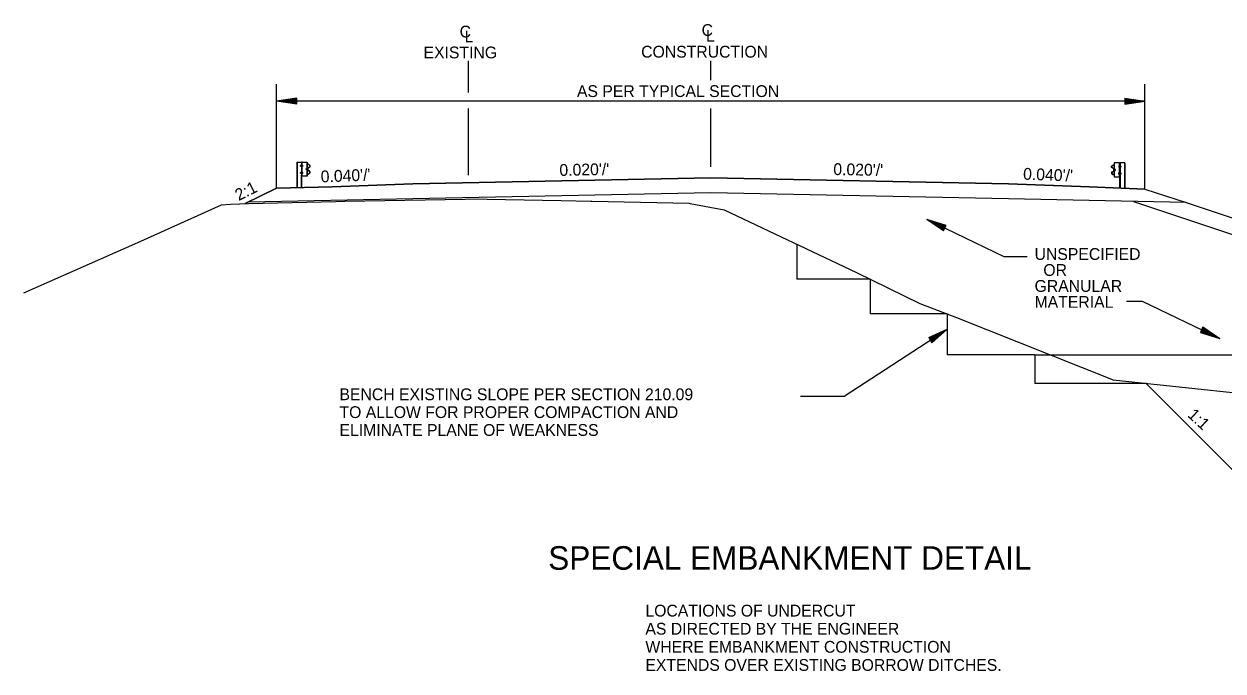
# Model space of a CAD drawing. Extents: x 1035 to 3550, y 35 to 1510.
# Drawn here: x 2159 to 2769, y 1181 to 1510 of the extents above; entities that cross this region are included whole.
import ezdxf

# ---------------------------------------------------------------- set-up
doc = ezdxf.new("R2010")
doc.units = 0
for name, color, linetype in [('G-ANNO-NPLT', 7, 'Continuous'), ('R_Alt Surface', 7, 'Continuous'), ('R_Border Notes', 7, 'Continuous'), ('R_Border Prem', 7, 'Continuous'), ('R_Exist Surface', 7, 'Continuous'), ('R_Fin Surface', 7, 'Continuous'), ('R_Grid', 7, 'Continuous')]:
    doc.layers.add(name, color=color, linetype=linetype)

msp = doc.modelspace()

# ---------------------------------------------------------------- linework, layer by layer
at = {"layer": 'G-ANNO-NPLT'}
for p, q in [((2385.15, 1474.91), (2385.15, 1491.12)), ((2508.51, 1481.13), (2508.51, 1491.12)), ((2385.15, 1432.87), (2385.15, 1466.73)), ((2508.51, 1437.15), (2508.51, 1466.73)), ((2297.65, 1439.46), (2297.65, 1426.52)), ((2297.81, 1439.46), (2297.81, 1426.52)), ((2299.71, 1437.35), (2299.71, 1437.83)), ((2299.99, 1437.76), (2299.74, 1437.76)), ((2299.99, 1437.43), (2299.74, 1437.43)), ((2299.99, 1437.27), (2299.74, 1437.27)), ((2299.99, 1437.91), (2299.75, 1437.91)), ((2299.99, 1437.43), (2299.77, 1437.43)), ((2299.99, 1437.27), (2299.99, 1437.91)), ((2300.35, 1439.47), (2300, 1439.45)), ((2300.18, 1426.52), (2300.18, 1439.47)), ((2300.35, 1439.47), (2300.32, 1439.47)), ((2300.64, 1437.56), (2300.35, 1437.56)), ((2300.38, 1437.24), (2300.64, 1437.24)), ((2300.39, 1437.89), (2300.64, 1437.89)), ((2300.64, 1437.89), (2300.64, 1437.24)), ((2302.57, 1435.69), (2302.57, 1436.18)), ((2302.85, 1436.1), (2302.6, 1436.1)), ((2302.85, 1435.77), (2302.6, 1435.77)), ((2302.85, 1435.62), (2302.6, 1435.62)), ((2302.85, 1436.26), (2302.61, 1436.26)), ((2302.85, 1435.77), (2302.63, 1435.77)), ((2302.85, 1435.62), (2302.85, 1436.26)), ((2302.92, 1432.43), (2302.92, 1439.43)), ((2303.66, 1438.36), (2303.08, 1438.67)), ((2303.59, 1438.28), (2303.12, 1438.53)), ((2303.12, 1435.62), (2303.13, 1436.3)), ((2303.24, 1435.62), (2303.25, 1436.3)), ((2304.13, 1434.74), (2303.34, 1435.24)), ((2303.36, 1436.65), (2304.25, 1437.19)), ((2304.2, 1434.84), (2303.4, 1435.34)), ((2303.43, 1436.54), (2304.31, 1437.08)), ((2304.26, 1437.74), (2303.59, 1438.28)), ((2304.33, 1437.82), (2303.66, 1438.36)), ((2712.67, 1437.46), (2713.34, 1438)), ((2713.57, 1436.18), (2712.69, 1436.72)), ((2712.74, 1437.38), (2713.41, 1437.92)), ((2713.64, 1436.29), (2712.76, 1436.83)), ((2713.34, 1438), (2713.92, 1438.31)), ((2713.41, 1437.92), (2713.89, 1438.17)), ((2713.76, 1435.26), (2713.75, 1435.94)), ((2713.88, 1435.26), (2713.87, 1435.94)), ((2714.08, 1432.07), (2714.08, 1439.07)), ((2714.15, 1435.26), (2714.15, 1435.9)), ((2714.15, 1435.9), (2714.4, 1435.9)), ((2714.15, 1435.74), (2714.4, 1435.74)), ((2714.15, 1435.41), (2714.37, 1435.41)), ((2714.15, 1435.41), (2714.4, 1435.41)), ((2714.15, 1435.26), (2714.41, 1435.26)), ((2714.43, 1435.34), (2714.43, 1435.82)), ((2716.61, 1437.53), (2716.36, 1437.53)), ((2716.36, 1437.53), (2716.36, 1436.88)), ((2716.62, 1436.88), (2716.36, 1436.88)), ((2716.37, 1437.2), (2716.66, 1437.2)), ((2716.65, 1439.11), (2716.68, 1439.11)), ((2716.65, 1439.11), (2717.01, 1439.09)), ((2716.83, 1426.16), (2716.83, 1439.11)), ((2717.01, 1436.91), (2717.01, 1437.55)), ((2717.01, 1437.55), (2717.26, 1437.55)), ((2717.01, 1437.4), (2717.26, 1437.4)), ((2717.01, 1437.07), (2717.23, 1437.07)), ((2717.01, 1437.07), (2717.26, 1437.07)), ((2717.01, 1436.91), (2717.27, 1436.91)), ((2717.29, 1436.99), (2717.29, 1437.47)), ((2719.2, 1439.1), (2719.2, 1426.16)), ((2719.35, 1439.1), (2719.35, 1426.16)), ((2299.66, 1433.8), (2299.66, 1434.29)), ((2299.94, 1434.37), (2299.69, 1434.37)), ((2299.94, 1434.21), (2299.69, 1434.21)), ((2299.94, 1433.88), (2299.69, 1433.88)), ((2299.94, 1433.72), (2299.69, 1433.72)), ((2299.94, 1433.88), (2299.72, 1433.88)), ((2299.94, 1433.72), (2299.94, 1434.37)), ((2300.35, 1432.43), (2300.17, 1432.43)), ((2300.64, 1434.04), (2300.35, 1434.04)), ((2300.64, 1433.72), (2300.38, 1433.72)), ((2300.64, 1434.37), (2300.39, 1434.37)), ((2300.64, 1433.72), (2300.64, 1434.37)), ((2303.06, 1433.27), (2303.62, 1433.55)), ((2303.11, 1433.17), (2303.69, 1433.47)), ((2303.62, 1433.55), (2304.27, 1434.11)), ((2303.69, 1433.47), (2304.34, 1434.03)), ((2713.31, 1433.11), (2712.66, 1433.67)), ((2713.38, 1433.19), (2712.74, 1433.75)), ((2712.81, 1434.48), (2713.6, 1434.98)), ((2712.87, 1434.38), (2713.67, 1434.88)), ((2713.9, 1432.81), (2713.31, 1433.11)), ((2713.94, 1432.91), (2713.38, 1433.19)), ((2716.36, 1433.37), (2716.36, 1434.01)), ((2716.36, 1434.01), (2716.61, 1434.01)), ((2716.36, 1433.37), (2716.62, 1433.37)), ((2716.37, 1433.68), (2716.66, 1433.68)), ((2716.66, 1432.07), (2716.83, 1432.07)), ((2717.06, 1433.37), (2717.06, 1434.01)), ((2717.06, 1434.01), (2717.31, 1434.01)), ((2717.06, 1433.85), (2717.32, 1433.85)), ((2717.06, 1433.52), (2717.28, 1433.52)), ((2717.06, 1433.52), (2717.32, 1433.52)), ((2717.06, 1433.37), (2717.32, 1433.37)), ((2717.34, 1433.44), (2717.34, 1433.93)), ((2287.37, 1426.32), (2271.45, 1418.36)), ((2315.65, 1426.88), (2287.37, 1426.32)), ((2701.36, 1426.88), (2729.63, 1425.75)), ((2552.43, 1397.62), (2552.43, 1379.93)), ((2589.68, 1379.93), (2552.43, 1379.93)), ((2589.68, 1379.93), (2589.68, 1362.24)), ((2628.97, 1362.24), (2589.68, 1362.24)), ((2628.97, 1362.24), (2628.97, 1341.5)), ((2576.51, 1320.45), (2628.97, 1354.51)), ((2619.51, 1350.2), (2628.97, 1354.51)), ((2619.51, 1350.2), (2621.19, 1347.61)), ((2619.65, 1349.99), (2627.53, 1353.57)), ((2619.79, 1349.77), (2626.05, 1352.61)), ((2619.93, 1349.55), (2624.61, 1351.68)), ((2620.07, 1349.33), (2623.15, 1350.73)), ((2620.21, 1349.11), (2621.71, 1349.79)), ((2620.48, 1348.71), (2621.71, 1349.79)), ((2620.62, 1348.49), (2623.15, 1350.73)), ((2620.76, 1348.27), (2624.61, 1351.68)), ((2620.9, 1348.05), (2626.05, 1352.61)), ((2621.05, 1347.83), (2627.53, 1353.57)), ((2621.19, 1347.61), (2628.97, 1354.51)), ((2673.51, 1341.5), (2628.97, 1341.5)), ((2673.51, 1341.5), (2673.51, 1326.86)), ((2673.51, 1341.5), (2957.97, 1341.5)), ((2730.27, 1326.86), (2673.51, 1326.86)), ((2730.27, 1326.86), (2776.48, 1280.64)), ((2554.26, 1320.45), (2576.51, 1320.45))]:
    msp.add_line(p, q, dxfattribs=at)
for points in [[(2297.65, 1439.46), (2300, 1439.45), (2299.99, 1426.52)], [(2719.35, 1439.1), (2717.01, 1439.09), (2717.01, 1426.16)], [(2723.83, 1419.54), (2957.97, 1341.5)], [(2669.72, 1391.34), (2658.01, 1391.34), (2618.48, 1410.37)], [(2720.2, 1368.78), (2728.28, 1368.78), (2767.8, 1349.75)]]:
    msp.add_lwpolyline(points, dxfattribs=at)
for points in [[(2299.7, 1437.75), (2299.7, 1437.43), (2299.57, 1437.43), (2299.57, 1437.75)], [(2299.99, 1438.01), (2299.99, 1437.15), (2300.04, 1437.15), (2300.04, 1438.01)], [(2303.05, 1439.46), (2303.05, 1432.43), (2300.35, 1432.43), (2300.35, 1439.47)], [(2300.64, 1437.89), (2300.64, 1437.24), (2300.35, 1437.24), (2300.35, 1437.89)], [(2302.56, 1436.1), (2302.56, 1435.78), (2302.43, 1435.78), (2302.43, 1436.1)], [(2302.85, 1436.36), (2302.85, 1435.5), (2302.9, 1435.5), (2302.9, 1436.36)], [(2713.95, 1439.1), (2713.96, 1432.07), (2716.66, 1432.07), (2716.65, 1439.11)], [(2714.16, 1436), (2714.16, 1435.14), (2714.1, 1435.14), (2714.1, 1436)], [(2714.44, 1435.74), (2714.44, 1435.42), (2714.57, 1435.42), (2714.57, 1435.74)], [(2716.37, 1437.53), (2716.37, 1436.88), (2716.65, 1436.88), (2716.65, 1437.53)], [(2717.02, 1437.65), (2717.02, 1436.79), (2716.96, 1436.79), (2716.96, 1437.65)], [(2717.3, 1437.39), (2717.3, 1437.07), (2717.43, 1437.07), (2717.43, 1437.39)], [(2299.64, 1434.21), (2299.64, 1433.88), (2299.52, 1433.88), (2299.52, 1434.21)], [(2299.93, 1434.47), (2299.93, 1433.61), (2299.98, 1433.61), (2299.98, 1434.47)], [(2300.64, 1434.37), (2300.64, 1433.72), (2300.35, 1433.72), (2300.35, 1434.37)], [(2716.37, 1434.01), (2716.37, 1433.37), (2716.65, 1433.37), (2716.65, 1434.01)], [(2717.07, 1434.11), (2717.07, 1433.25), (2717.02, 1433.25), (2717.02, 1434.11)], [(2717.36, 1433.85), (2717.36, 1433.52), (2717.49, 1433.52), (2717.49, 1433.85)]]:
    msp.add_lwpolyline(points, close=True, dxfattribs=at)
for centre, radius, start, end in [((2299.83, 1437.83), 0.113, 134.57445, 222.22441), ((2300.19, 1437.59), 0.474, 159.74227, 200.25773), ((2299.84, 1437.35), 0.128, 140.93341, 216.62337), ((2302.69, 1436.18), 0.113, 134.57445, 222.22441), ((2303.05, 1435.94), 0.474, 159.74227, 200.25773), ((2302.7, 1435.69), 0.128, 140.93341, 216.62337), ((2303.48, 1435.57), 0.362, 171.78044, 246.85364), ((2303.57, 1436.26), 0.445, 118.10599, 175.04439), ((2303.22, 1435.91), 0.233, 282.95537, 86.06973), ((2303.48, 1435.57), 0.237, 171.78044, 246.85364), ((2303.57, 1436.26), 0.32, 118.10599, 175.04439), ((2304.09, 1437.47), 0.319, 299.24991, 57.97825), ((2304.09, 1437.47), 0.44, 299.24991, 57.97825), ((2712.91, 1437.11), 0.44, 122.02175, 240.75009), ((2712.91, 1437.11), 0.319, 122.02175, 240.75009), ((2713.79, 1435.55), 0.233, 93.93027, 257.04463), ((2713.43, 1435.9), 0.32, 4.95561, 61.89401), ((2713.53, 1435.21), 0.237, 293.14636, 8.21956), ((2713.43, 1435.9), 0.445, 4.95561, 61.89401), ((2713.53, 1435.21), 0.362, 293.14636, 8.21956), ((2714.32, 1435.82), 0.113, 317.77559, 45.42555), ((2713.96, 1435.58), 0.474, 339.74227, 20.25773), ((2714.3, 1435.33), 0.128, 323.37663, 39.06659), ((2717.18, 1437.47), 0.113, 317.77559, 45.42555), ((2716.82, 1437.23), 0.474, 339.74227, 20.25773), ((2717.16, 1436.99), 0.128, 323.37663, 39.06659), ((2299.77, 1434.29), 0.113, 134.57445, 222.22441), ((2300.13, 1434.05), 0.474, 159.74227, 200.25773), ((2299.79, 1433.8), 0.128, 140.93341, 216.62337), ((2303.91, 1434.36), 0.439, 325.21842, 59.11995), ((2303.91, 1434.36), 0.562, 325.21843, 59.11995), ((2713.1, 1434), 0.562, 120.88005, 214.78158), ((2713.1, 1434), 0.439, 120.88005, 214.78158), ((2717.23, 1433.93), 0.113, 317.77559, 45.42555), ((2716.87, 1433.69), 0.474, 339.74227, 20.25773), ((2717.22, 1433.44), 0.128, 323.37663, 39.06659)]:
    msp.add_arc(centre, radius, start, end, dxfattribs=at)
at = {"layer": 'R_Alt Surface'}
msp.add_lwpolyline([(2750.59, 1419.01), (2660.22, 1420.82), (2508.51, 1423.85), (2356.79, 1420.82), (2273.01, 1419.14)], dxfattribs=at)
at = {"layer": 'R_Border Prem'}
for p, q in [((2287.37, 1426.32), (2287.37, 1479.09)), ((2729.63, 1425.75), (2729.63, 1479.09)), ((2729.63, 1470.53), (2287.37, 1470.53))]:
    msp.add_line(p, q, dxfattribs=at)
at = {"layer": 'R_Exist Surface'}
msp.add_lwpolyline([(2158.74, 1372.95), (2218.29, 1399.28), (2259.33, 1417.8), (2263.85, 1418.02), (2273.08, 1418.43), (2317.62, 1419.48), (2322.1, 1419.59), (2383.45, 1420.71), (2385.15, 1420.74), (2432.34, 1419.95), (2447.44, 1419.7), (2447.87, 1419.69), (2497.47, 1418.55), (2497.97, 1418.46), (2515.31, 1415.16), (2582.82, 1383.26), (2615, 1367.62), (2633.7, 1360.42), (2713.47, 1328.62), (2815.79, 1317.9), (2829.33, 1316.58), (2835.72, 1315.51)], dxfattribs=at)
at = {"layer": 'R_Fin Surface'}
for points in [[(2271.45, 1418.36), (2287.37, 1426.32), (2315.65, 1426.88), (2356.79, 1428.53), (2508.51, 1431.56), (2660.22, 1428.53), (2701.36, 1426.88), (2729.63, 1425.75), (2750.59, 1419.01), (3048.58, 1319.43)], [(2729.63, 1425.75), (2701.36, 1426.88), (2660.22, 1428.53), (2508.51, 1431.56), (2356.79, 1428.53), (2315.65, 1426.88), (2287.37, 1426.32)]]:
    msp.add_lwpolyline(points, dxfattribs=at)
at = {"layer": 'R_Grid'}
for p, q in [((2297.66, 1472.07), (2287.37, 1470.53)), ((2297.66, 1471.81), (2289.09, 1470.53)), ((2297.66, 1468.98), (2297.66, 1472.07)), ((2719.34, 1472.07), (2729.63, 1470.53)), ((2719.34, 1472.07), (2719.34, 1468.98)), ((2719.34, 1471.81), (2727.91, 1470.53)), ((2297.66, 1468.98), (2287.37, 1470.53)), ((2297.66, 1469.24), (2289.09, 1470.53)), ((2297.66, 1471.55), (2290.86, 1470.53)), ((2297.66, 1469.5), (2290.86, 1470.53)), ((2297.66, 1471.29), (2292.57, 1470.53)), ((2297.66, 1469.76), (2292.57, 1470.53)), ((2297.66, 1471.03), (2294.31, 1470.53)), ((2297.66, 1470.03), (2294.31, 1470.53)), ((2297.66, 1470.77), (2296.03, 1470.53)), ((2297.66, 1470.29), (2296.03, 1470.53)), ((2719.34, 1471.55), (2726.14, 1470.53)), ((2719.34, 1471.29), (2724.43, 1470.53)), ((2719.34, 1471.03), (2722.68, 1470.53)), ((2719.34, 1470.77), (2720.97, 1470.53)), ((2719.34, 1468.98), (2729.63, 1470.53)), ((2719.34, 1470.02), (2722.68, 1470.53)), ((2719.34, 1469.5), (2726.14, 1470.53)), ((2719.34, 1469.24), (2727.91, 1470.53)), ((2719.34, 1469.76), (2724.43, 1470.53)), ((2719.34, 1470.29), (2720.97, 1470.53)), ((2627.08, 1404.52), (2618.48, 1410.37)), ((2628.42, 1407.3), (2618.48, 1410.37)), ((2627.19, 1404.75), (2620.03, 1409.63)), ((2628.31, 1407.07), (2620.03, 1409.63)), ((2628.2, 1406.83), (2621.63, 1408.86)), ((2627.31, 1404.99), (2621.63, 1408.86)), ((2627.42, 1405.22), (2623.17, 1408.12)), ((2628.08, 1406.6), (2623.17, 1408.12)), ((2627.97, 1406.37), (2624.74, 1407.36)), ((2627.53, 1405.46), (2624.74, 1407.36)), ((2627.86, 1406.13), (2626.29, 1406.62)), ((2627.65, 1405.69), (2626.29, 1406.62)), ((2627.08, 1404.52), (2628.42, 1407.3)), ((2759.2, 1355.6), (2757.87, 1352.82)), ((2757.87, 1352.82), (2767.8, 1349.75)), ((2757.98, 1353.06), (2766.26, 1350.5)), ((2758.09, 1353.29), (2764.66, 1351.26)), ((2758.2, 1353.52), (2763.12, 1352.01)), ((2758.32, 1353.76), (2761.55, 1352.76)), ((2758.43, 1354), (2760, 1353.51)), ((2758.64, 1354.43), (2760, 1353.51)), ((2758.75, 1354.66), (2761.55, 1352.76)), ((2758.87, 1354.9), (2763.12, 1352.01)), ((2758.98, 1355.14), (2764.66, 1351.26)), ((2759.09, 1355.37), (2766.26, 1350.5)), ((2759.2, 1355.6), (2767.8, 1349.75))]:
    msp.add_line(p, q, dxfattribs=at)

# ---------------------------------------------------------------- texts
at = {"layer": 'G-ANNO-NPLT'}
for s, height, p in [('C', 6, (2380.61, 1502.93)), ('C', 6, (2503.86, 1503.71)), ('L', 6, (2383.13, 1500.43)), ('L', 6, (2506.12, 1500.82)), ('EXISTING', 6, (2362.23, 1492.31)), ('CONSTRUCTION', 6, (2473.08, 1492.69)), ('UNSPECIFIED', 6, (2673.44, 1389.73)), ('  OR', 6, (2673.44, 1381.6)), ('GRANULAR', 6, (2673.44, 1373.47)), ('MATERIAL', 6, (2673.44, 1365.35)), ('BENCH EXISTING SLOPE PER SECTION 210.09', 6, (2319.42, 1318.34)), ('TO ALLOW FOR PROPER COMPACTION AND', 6, (2319.42, 1309.25)), ('ELIMINATE PLANE OF WEAKNESS', 6, (2319.42, 1300.17)), ('SPECIAL EMBANKMENT DETAIL', 12, (2425.76, 1232.04)), ('LOCATIONS OF UNDERCUT', 6, (2475.23, 1208.23)), ('AS DIRECTED BY THE ENGINEER', 6, (2475.23, 1199.02)), ('WHERE EMBANKMENT CONSTRUCTION ', 6, (2475.23, 1189.81)), ('EXTENDS OVER EXISTING BORROW DITCHES.', 6, (2475.23, 1180.59))]:
    msp.add_text(s, height=height, dxfattribs=at).set_placement(p)
msp.add_text('2:1', height=6, rotation=26.565, dxfattribs=at).set_placement((2268.09, 1419.67))
at = {"layer": 'R_Border Notes'}
for s, rotation, p in [("0.040'/'", 2.29061, (2309.99, 1429.15)), ("0.020'/'", 1.14576, (2431.49, 1432.47)), ("0.020'/'", 358.85424, (2570.89, 1432.96)), ("0.040'/'", 357.70939, (2667.5, 1430.61)), ('1:1', 317.17444, (2750.96, 1310.28))]:
    msp.add_text(s, height=6, rotation=rotation, dxfattribs=at).set_placement(p)
at = {"layer": 'R_Border Prem'}
msp.add_text('AS PER TYPICAL SECTION', height=6, dxfattribs=at).set_placement((2440.37, 1472.63))

doc.saveas('drawing.dxf')
